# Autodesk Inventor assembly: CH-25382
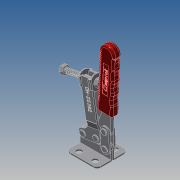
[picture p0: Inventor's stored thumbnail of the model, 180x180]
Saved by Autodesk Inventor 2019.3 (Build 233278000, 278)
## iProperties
Company: Î¢ÈíÖÐ¹ú
Created: 2012-09
Part Number: CH-25382
Material: Ogólny
Description: STEP AP203
Document SubType Name: Assembly
Designer: CADENGINEERING4
Stock Number: DOCISKI POZIOME
Sending System: SolidWorks 2010
Preprocessor: SwSTEP 2.0
Title: CH-25382.STEP
Author: Î¢ÈíÓÃ»§
Revision Number: ÈÎºÎ
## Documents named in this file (10)
- E:\STRONA\Horizontal toggle clamp\CH-25382\CH-25382_OTWARTY.iam
- E:\STRONA\Horizontal toggle clamp\CH-25382\25382-04.ipt
- E:\STRONA\Horizontal toggle clamp\CH-25382\25382-05.ipt
- E:\STRONA\Horizontal toggle clamp\CH-25382\25382-02.ipt
- E:\STRONA\Horizontal toggle clamp\CH-25382\FW380.ipt
- E:\STRONA\Horizontal toggle clamp\CH-25382\M8.ipt
- E:\STRONA\Horizontal toggle clamp\CH-25382\25382-03.ipt
- E:\STRONA\Horizontal toggle clamp\CH-25382\086512.ipt
- E:\STRONA\Horizontal toggle clamp\CH-25382\01.ipt
- E:\STRONA\Horizontal toggle clamp\CH-25382\25382-01.ipt
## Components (15 placed, 15 different names)
1. 25382-04_1 — Zestawiające:13, Zestawiające:16, Zestawiające:17, Zestawiające:19, Zestawiające:24, Zestawiające:25, Zestawiające:26, Zestawiające:27, Styczny:1
2. 25382-05_2 — Zestawiające:22, Zestawiające:23
3. 25382-02_3 — Równoległe:2, Zestawiające:7, Zestawiające:9, Zestawiające:12, Zestawiające:20, Zestawiające:21, Zestawiające:23, Zestawiające:28, Zestawiające:29, Zestawiające:30, Styczny:1
4. FW380_4 — Równoległe:3, Zestawiające:8, Zestawiające:9, Zestawiające:11
5. M8_5 — Zestawiające:10, Zestawiające:11
6. 25382-05_6 — Zestawiające:29, Zestawiające:30
7. 25382-03_7 — Zestawiające:1, Zestawiające:2, Zestawiające:3, Zestawiające:24, Zestawiające:25, Zestawiające:28
8. 086512_8 — Równoległe:1, Zestawiające:4, Zestawiające:5, Zestawiające:8, Zestawiające:10, Zestawiające:12
9. 01_9 — Zestawiające:1, Zestawiające:2, Zestawiające:3
10. 25382-05_10 — Zestawiające:26, Zestawiające:27
11. 25382-01_11 — Zestawiające:13, Zestawiające:14, Zestawiające:15, Zestawiające:16, Zestawiające:18, Zestawiające:20, Zestawiające:21, Zestawiające:22
12. 25382-04_12 — Zestawiające:14, Zestawiające:15, Zestawiające:17
13. FW380_13 — Równoległe:2, Równoległe:3, Zestawiające:5, Zestawiające:6, Zestawiające:7
14. 25382-05_14 — Zestawiające:18, Zestawiające:19
15. M8_15 — Równoległe:1, Zestawiające:4, Zestawiające:6
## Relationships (34: Mate 30, Flush 3, Tangent 1)
- Równoległe:1 [Flush]: 086512_8 ↔ M8_15
- Równoległe:2 [Flush]: 25382-02_3 ↔ FW380_13
- Równoległe:3 [Flush]: FW380_4 ↔ FW380_13
- Zestawiające:1 [Mate]: 25382-03_7 ↔ 01_9
- Zestawiające:2 [Mate]: 25382-03_7 ↔ 01_9
- Zestawiające:3 [Mate]: 25382-03_7 ↔ 01_9
- Zestawiające:4 [Mate]: 086512_8 ↔ M8_15
- Zestawiające:5 [Mate]: 086512_8 ↔ FW380_13
- Zestawiające:6 [Mate]: FW380_13 ↔ M8_15
- Zestawiające:7 [Mate]: 25382-02_3 ↔ FW380_13
- Zestawiające:8 [Mate]: FW380_4 ↔ 086512_8
- Zestawiające:9 [Mate]: 25382-02_3 ↔ FW380_4
- Zestawiające:10 [Mate]: M8_5 ↔ 086512_8
- Zestawiające:11 [Mate]: FW380_4 ↔ M8_5
- Zestawiające:12 [Mate]: 25382-02_3 ↔ 086512_8
- Zestawiające:13 [Mate]: 25382-04_1 ↔ 25382-01_11
- Zestawiające:14 [Mate]: 25382-01_11 ↔ 25382-04_12
- Zestawiające:15 [Mate]: 25382-01_11 ↔ 25382-04_12
- Zestawiające:16 [Mate]: 25382-04_1 ↔ 25382-01_11
- Zestawiające:17 [Mate]: 25382-04_1 ↔ 25382-04_12
- Zestawiające:18 [Mate]: 25382-01_11 ↔ 25382-05_14
- Zestawiające:19 [Mate]: 25382-04_1 ↔ 25382-05_14
- Zestawiające:20 [Mate]: 25382-02_3 ↔ 25382-01_11
- Zestawiające:21 [Mate]: 25382-02_3 ↔ 25382-01_11
- Zestawiające:22 [Mate]: 25382-05_2 ↔ 25382-01_11
- Zestawiające:23 [Mate]: 25382-05_2 ↔ 25382-02_3
- Zestawiające:24 [Mate]: 25382-04_1 ↔ 25382-03_7
- Zestawiające:25 [Mate]: 25382-04_1 ↔ 25382-03_7
- Zestawiające:26 [Mate]: 25382-04_1 ↔ 25382-05_10
- Zestawiające:27 [Mate]: 25382-04_1 ↔ 25382-05_10
- Zestawiające:28 [Mate]: 25382-02_3 ↔ 25382-03_7
- Zestawiające:29 [Mate]: 25382-02_3 ↔ 25382-05_6
- Zestawiające:30 [Mate]: 25382-02_3 ↔ 25382-05_6
- Styczny:1 [Tangent]: 25382-04_1 ↔ 25382-02_3
